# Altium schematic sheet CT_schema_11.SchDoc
size 281 x 153 mm
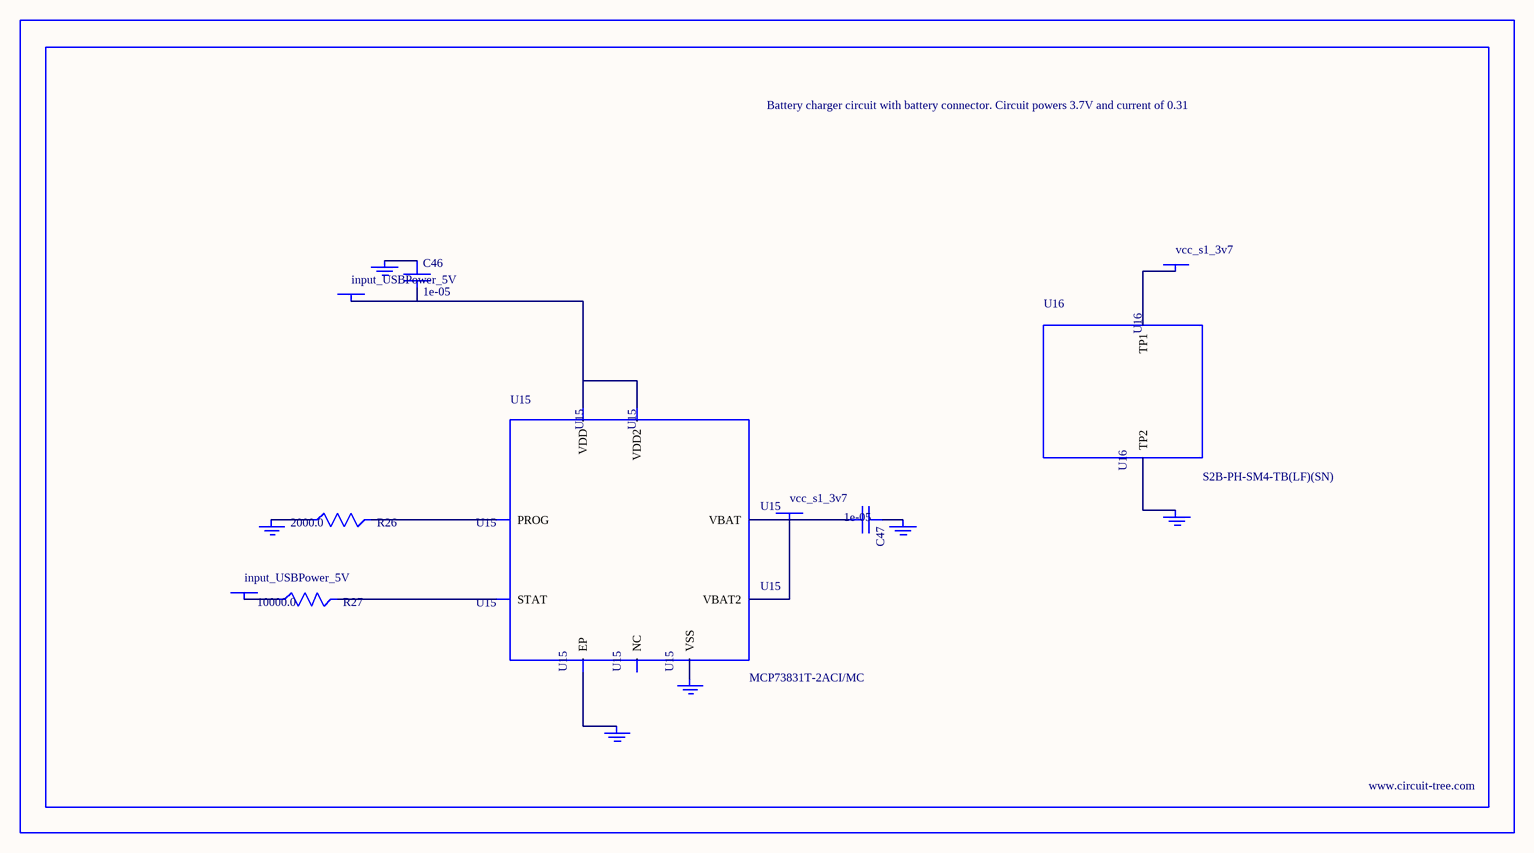
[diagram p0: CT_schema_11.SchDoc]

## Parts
BORDER10  (no value)
C46  1e-05  [C1206]
C47  1e-05  [C1206]
GND_INSTANCE_10_0  (no value)
GND_INSTANCE_10_1  (no value)
GND_INSTANCE_10_2  (no value)
GND_INSTANCE_10_3  (no value)
GND_INSTANCE_10_4  (no value)
GND_INSTANCE_10_5  (no value)
POWER_INSTANCE_10_0  input_USBPower_5V
POWER_INSTANCE_10_1  input_USBPower_5V
POWER_INSTANCE_10_2  vcc_s1_3v7
POWER_INSTANCE_10_3  vcc_s1_3v7
R26  2000.0  [R0603]
R27  10000.0  [R0603]
U15  MCP73831T-2ACI/MC  [DFN8_2X3MC]
U16  S2B-PH-SM4-TB(LF)(SN)  [JST-2-SMD]

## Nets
NetC46_1: C46.1 GND_INSTANCE_10_0.0(GND)
NetC46_2: C46.2 POWER_INSTANCE_10_0.0(PWR) U15.1(VDD) U15.2(VDD2)
NetC47_1: C47.1 GND_INSTANCE_10_1.0(GND)
NetC47_2: C47.2 POWER_INSTANCE_10_2.0(PWR) U15.3(VBAT) U15.4(VBAT2)
NetGND_INSTANCE_10_2_0: GND_INSTANCE_10_2.0(GND) R26.1
NetGND_INSTANCE_10_3_0: GND_INSTANCE_10_3.0(GND) U15.9(EP)
NetGND_INSTANCE_10_4_0: GND_INSTANCE_10_4.0(GND) U15.6(VSS)
NetGND_INSTANCE_10_5_0: GND_INSTANCE_10_5.0(GND) U16.2(TP2)
NetPOWER_INSTANCE_10_1_0: POWER_INSTANCE_10_1.0(PWR) R27.1
NetPOWER_INSTANCE_10_3_0: POWER_INSTANCE_10_3.0(PWR) U16.1(TP1)
NetR26_2: R26.2 U15.8(PROG)
NetR27_2: R27.2 U15.5(STAT)

Not connected (* = marked no-connect by the designer): U15 7(NC)

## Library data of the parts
BORDER10 = BORDER_PAGE10
C46 C47 = C1206C106K3RACTU
GND_INSTANCE_10_0-GND_INSTANCE_10_5 = GND
POWER_INSTANCE_10_0-POWER_INSTANCE_10_3 = PWR
R26 = RC0603JR-072KL
R27 = RC0603JR-0710KL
